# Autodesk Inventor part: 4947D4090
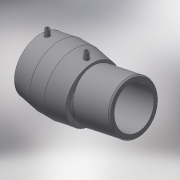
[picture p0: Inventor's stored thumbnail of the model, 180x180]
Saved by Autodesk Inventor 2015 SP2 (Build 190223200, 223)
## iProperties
Created: 2017-06
Part Number: 4947D4090
Material: Generic
Description: PLASSON ADJUSTABLE ELBOW (ONE SIDE) 90
Document SubType Name: Modeling
Designer: KIM
Mass: 55.0731 g
Surface Area: 148.067 cm^2
Volume: 55.0731 cm^3
Density: 1 g/cm^3
Appearance: Default
Author: KIM
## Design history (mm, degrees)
derived "4947D4.ipt"
feature "Solid1::4947D4.ipt"
tag "TaggingFeature1"
body "Solid1"
other parameters: "d0" = 135.45, "d2" = 116, "d3" = 72, "d4" = 36, "d5" = 104.4, "d8" = 168 deg, "d10" = 28.8, "d11" = 9.6, "d29" = 77, "d30" = 15, "d31" = 51.6, "d34" = 5 deg, "d41" = 4, "d42" = 14, "d43" = 0, "d48" = 81, "d55" = 38.07, "d57" = 168 deg, "d62" = 3, "d63" = 0, "d65" = 258, "d67" = 81, "d68" = 135 deg, "d69" = 82, "d70" = 42.92, "d71" = 2.32, "L_" = 258, "L_1" = 72, "D_" = 116, "A_" = 77, "d_2" = 12, "L_0" = 148, "L_2" = 82, "d54" = 63.45, "d59" = 161.3813
